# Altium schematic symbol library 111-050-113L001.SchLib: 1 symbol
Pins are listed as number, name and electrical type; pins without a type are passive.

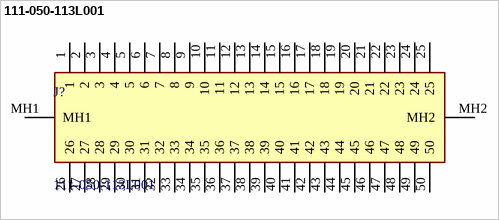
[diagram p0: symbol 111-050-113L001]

## 111-050-113L001
designator J?
NORCOMP - 111-050-113L001 - CONNECTOR, SCSI, PLUG, 50 POSITION, SOLDER; Geometry.Height: 12.55mm
footprint 111050113L001
pins: 1, 2, 3, 4, 5, 6, 7, 8, 9, 10, 11, 12, 13, 14, 15, 16, 17, 18, 19, 20, 21, 22, 23, 24, 25, 26, 27, 28, 29, 30, 31, 32, 33, 34, 35, 36, 37, 38, 39, 40, 41, 42, 43, 44, 45, 46, 47, 48, 49, 50, MH1, MH2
